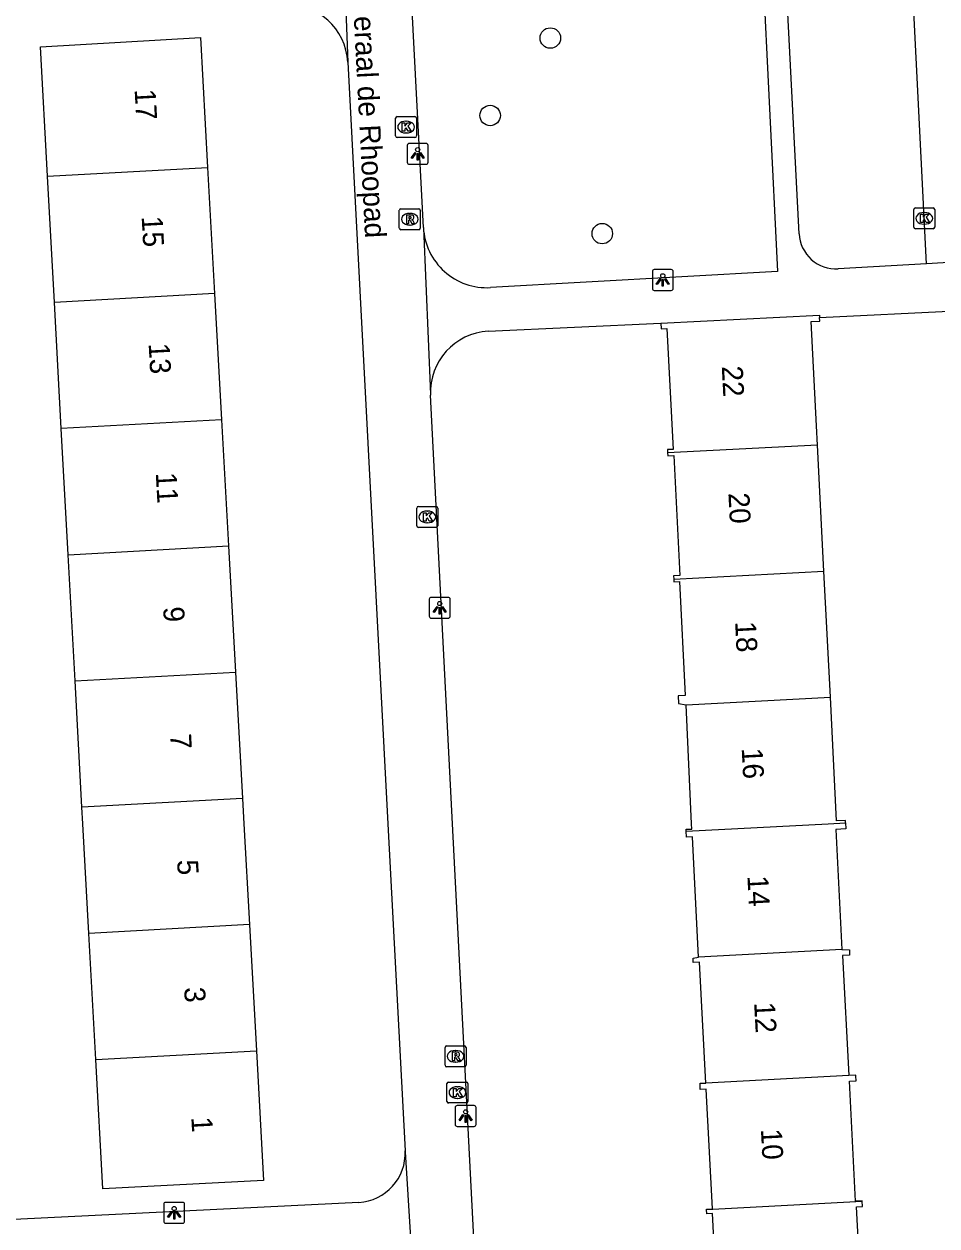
# Model space of a CAD drawing. Extents: x 161084 to 161928, y 385355 to 386522.
# Drawn here: x 161345.5 to 161389.2, y 385480.8 to 385538.2 of the extents above; entities that cross this region are included whole.
import ezdxf

# ---------------------------------------------------------------- set-up
doc = ezdxf.new("R2010")
doc.units = 0
for name, color, linetype in [('IMGEO_Boom', 7, 'Continuous'), ('IMGEO_Kolk', 7, 'Continuous'), ('IMGEO_Lichtpunt', 7, 'Continuous'), ('IMGEO_Muur', 7, 'Continuous'), ('IMGEO_Openbare_ruimte_label', 7, 'Continuous'), ('IMGEO_Pand', 7, 'Continuous'), ('IMGEO_Pand_nummerreeks', 7, 'Continuous'), ('IMGEO_Rijbaan_lokaal_open', 7, 'Continuous'), ('IMGEO_Rioolput', 7, 'Continuous'), ('IMGEO_Voetpad_open', 7, 'Continuous')]:
    doc.layers.add(name, color=color, linetype=linetype)

msp = doc.modelspace()

# ---------------------------------------------------------------- linework, layer by layer
at = {"layer": 'IMGEO_Boom'}
for centre in [(161370.683, 385537.575), (161367.806, 385533.87), (161373.165, 385528.221)]:
    msp.add_circle(centre, 0.489, dxfattribs=at)
at = {"layer": 'IMGEO_Kolk'}
for p, q in [((161363.289, 385532.891), (161363.289, 385533.743)), ((161363.364, 385533.817), (161364.216, 385533.817)), ((161363.777, 385533.597), (161363.802, 385533.597)), ((161364.29, 385533.743), (161364.29, 385532.891)), ((161363.8, 385533.037), (161363.775, 385533.037)), ((161364.216, 385532.817), (161363.364, 385532.817)), ((161388.056, 385528.527), (161388.056, 385529.379)), ((161388.131, 385529.453), (161388.983, 385529.453)), ((161388.544, 385529.233), (161388.569, 385529.233)), ((161389.057, 385529.379), (161389.057, 385528.527)), ((161388.983, 385528.453), (161388.131, 385528.453)), ((161388.567, 385528.673), (161388.542, 385528.673)), ((161364.303, 385514.248), (161364.303, 385515.1)), ((161364.378, 385515.174), (161365.23, 385515.174)), ((161364.791, 385514.954), (161364.816, 385514.954)), ((161365.304, 385515.1), (161365.304, 385514.248)), ((161365.23, 385514.174), (161364.378, 385514.174)), ((161364.814, 385514.394), (161364.789, 385514.394)), ((161365.818, 385487.651), (161366.67, 385487.651)), ((161365.743, 385486.725), (161365.743, 385487.577)), ((161366.231, 385487.431), (161366.256, 385487.431)), ((161366.744, 385487.577), (161366.744, 385486.725)), ((161366.67, 385486.651), (161365.818, 385486.651)), ((161366.254, 385486.871), (161366.229, 385486.871))]:
    msp.add_line(p, q, dxfattribs=at)
for points in [[(161363.289, 385532.891), (161363.289, 385533.743)], [(161363.364, 385533.817), (161364.216, 385533.817)], [(161364.29, 385533.743), (161364.29, 385532.891)], [(161363.61, 385533.517), (161363.733, 385533.517), (161363.733, 385533.366), (161363.863, 385533.517), (161364.027, 385533.517), (161363.881, 385533.366), (161364.034, 385533.117), (161363.882, 385533.117), (161363.797, 385533.281), (161363.733, 385533.214), (161363.733, 385533.117), (161363.61, 385533.117), (161363.61, 385533.517)], [(161364.216, 385532.817), (161363.364, 385532.817)], [(161388.056, 385528.527), (161388.056, 385529.379)], [(161388.131, 385529.453), (161388.983, 385529.453)], [(161388.377, 385529.153), (161388.5, 385529.153), (161388.5, 385529.002), (161388.63, 385529.153), (161388.794, 385529.153), (161388.648, 385529.002), (161388.801, 385528.753), (161388.649, 385528.753), (161388.564, 385528.917), (161388.5, 385528.85), (161388.5, 385528.753), (161388.377, 385528.753), (161388.377, 385529.153)], [(161389.057, 385529.379), (161389.057, 385528.527)], [(161388.983, 385528.453), (161388.131, 385528.453)], [(161364.303, 385514.248), (161364.303, 385515.1)], [(161364.378, 385515.174), (161365.23, 385515.174)], [(161364.624, 385514.874), (161364.747, 385514.874), (161364.747, 385514.723), (161364.877, 385514.874), (161365.041, 385514.874), (161364.895, 385514.723), (161365.048, 385514.474), (161364.896, 385514.474), (161364.811, 385514.638), (161364.747, 385514.571), (161364.747, 385514.474), (161364.624, 385514.474), (161364.624, 385514.874)], [(161365.304, 385515.1), (161365.304, 385514.248)], [(161365.23, 385514.174), (161364.378, 385514.174)], [(161365.818, 385487.651), (161366.67, 385487.651)], [(161365.743, 385486.725), (161365.743, 385487.577)], [(161366.064, 385487.351), (161366.187, 385487.351), (161366.187, 385487.2), (161366.317, 385487.351), (161366.481, 385487.351), (161366.335, 385487.2), (161366.488, 385486.951), (161366.336, 385486.951), (161366.251, 385487.115), (161366.187, 385487.048), (161366.187, 385486.951), (161366.064, 385486.951), (161366.064, 385487.351)], [(161366.744, 385487.577), (161366.744, 385486.725)], [(161366.67, 385486.651), (161365.818, 385486.651)]]:
    msp.add_lwpolyline(points, dxfattribs=at)
for centre, start, end in [((161363.366, 385533.741), 91.55205, 178.44795), ((161363.366, 385533.741), 91.55205, 178.44795), ((161364.214, 385533.741), 1.55205, 88.44795), ((161364.214, 385533.741), 1.55205, 88.44795), ((161363.366, 385532.893), 181.55205, 268.44795), ((161363.366, 385532.893), 181.55205, 268.44795), ((161364.214, 385532.893), 271.55205, 358.44795), ((161364.214, 385532.893), 271.55205, 358.44795), ((161388.133, 385529.377), 91.55205, 178.44795), ((161388.133, 385529.377), 91.55205, 178.44795), ((161388.981, 385529.377), 1.55205, 88.44795), ((161388.981, 385529.377), 1.55205, 88.44795), ((161388.133, 385528.529), 181.55205, 268.44795), ((161388.133, 385528.529), 181.55205, 268.44795), ((161388.981, 385528.529), 271.55205, 358.44795), ((161388.981, 385528.529), 271.55205, 358.44795), ((161364.38, 385515.098), 91.55205, 178.44795), ((161364.38, 385515.098), 91.55205, 178.44795), ((161365.228, 385515.098), 1.55205, 88.44795), ((161365.228, 385515.098), 1.55205, 88.44795), ((161364.38, 385514.25), 181.55205, 268.44795), ((161364.38, 385514.25), 181.55205, 268.44795), ((161365.228, 385514.25), 271.55205, 358.44795), ((161365.228, 385514.25), 271.55205, 358.44795), ((161365.82, 385487.575), 91.55205, 178.44795), ((161365.82, 385487.575), 91.55205, 178.44795), ((161366.668, 385487.575), 1.55205, 88.44795), ((161366.668, 385487.575), 1.55205, 88.44795), ((161365.82, 385486.727), 181.55205, 268.44795), ((161365.82, 385486.727), 181.55205, 268.44795), ((161366.668, 385486.727), 271.55205, 358.44795), ((161366.668, 385486.727), 271.55205, 358.44795)]:
    msp.add_arc(centre, 0.0765, start, end, dxfattribs=at)
for centre, major_axis, ratio, start_param, end_param in [((161363.776, 385533.317), (-0.387, 0.002), 0.722429, 4.712389, 7.853982), ((161363.801, 385533.317), (-0.39, 0.002), 0.717154, 1.570796, 4.712389), ((161388.543, 385528.953), (-0.387, 0.002), 0.722429, 4.712389, 7.853982), ((161388.568, 385528.953), (-0.39, 0.002), 0.717154, 1.570796, 4.712389), ((161364.79, 385514.674), (-0.387, 0.002), 0.722429, 4.712389, 7.853982), ((161364.815, 385514.674), (-0.39, 0.002), 0.717154, 1.570796, 4.712389), ((161366.23, 385487.151), (-0.387, 0.002), 0.722429, 4.712389, 7.853982), ((161366.255, 385487.151), (-0.39, 0.002), 0.717154, 1.570796, 4.712389)]:
    msp.add_ellipse(centre, major_axis=major_axis, ratio=ratio, start_param=start_param, end_param=end_param, dxfattribs=at)
at = {"layer": 'IMGEO_Lichtpunt'}
for p, q in [((161363.848, 385532.439), (161363.848, 385531.632)), ((161363.848, 385532.439), (161363.848, 385531.632)), ((161364.75, 385532.534), (161363.942, 385532.534)), ((161364.75, 385532.534), (161363.942, 385532.534)), ((161364.844, 385531.632), (161364.844, 385532.439)), ((161364.844, 385531.632), (161364.844, 385532.439)), ((161363.942, 385531.538), (161364.75, 385531.538)), ((161363.942, 385531.538), (161364.75, 385531.538)), ((161375.56, 385526.409), (161375.56, 385525.602)), ((161375.56, 385526.409), (161375.56, 385525.602)), ((161376.462, 385526.504), (161375.654, 385526.504)), ((161376.462, 385526.504), (161375.654, 385526.504)), ((161376.556, 385525.602), (161376.556, 385526.409)), ((161376.556, 385525.602), (161376.556, 385526.409)), ((161375.654, 385525.508), (161376.462, 385525.508)), ((161375.654, 385525.508), (161376.462, 385525.508)), ((161364.9, 385510.735), (161364.9, 385509.928)), ((161364.9, 385510.735), (161364.9, 385509.928)), ((161365.802, 385510.83), (161364.994, 385510.83)), ((161365.802, 385510.83), (161364.994, 385510.83)), ((161365.896, 385509.928), (161365.896, 385510.735)), ((161365.896, 385509.928), (161365.896, 385510.735)), ((161364.994, 385509.834), (161365.802, 385509.834)), ((161364.994, 385509.834), (161365.802, 385509.834)), ((161367.038, 385486.526), (161366.23, 385486.526)), ((161367.038, 385486.526), (161366.23, 385486.526)), ((161366.136, 385486.431), (161366.136, 385485.624)), ((161366.136, 385486.431), (161366.136, 385485.624)), ((161367.132, 385485.624), (161367.132, 385486.431)), ((161367.132, 385485.624), (161367.132, 385486.431)), ((161366.23, 385485.53), (161367.038, 385485.53)), ((161366.23, 385485.53), (161367.038, 385485.53)), ((161353.11, 385481.9), (161352.302, 385481.9)), ((161353.11, 385481.9), (161352.302, 385481.9)), ((161352.208, 385481.805), (161352.208, 385480.998)), ((161352.208, 385481.805), (161352.208, 385480.998)), ((161353.204, 385480.998), (161353.204, 385481.805)), ((161353.204, 385480.998), (161353.204, 385481.805)), ((161352.302, 385480.904), (161353.11, 385480.904)), ((161352.302, 385480.904), (161353.11, 385480.904))]:
    msp.add_line(p, q, dxfattribs=at)
for points in [[(161364.222, 385532.103), (161364.261, 385532.075), (161364.073, 385531.813), (161364.035, 385531.84), (161364.222, 385532.103)], [(161364.324, 385532.055), (161364.371, 385532.055), (161364.371, 385531.733), (161364.324, 385531.733), (161364.324, 385532.055)], [(161364.434, 385532.075), (161364.472, 385532.102), (161364.659, 385531.84), (161364.62, 385531.812), (161364.434, 385532.075)], [(161375.934, 385526.073), (161375.973, 385526.045), (161375.785, 385525.783), (161375.747, 385525.81), (161375.934, 385526.073)], [(161376.036, 385526.025), (161376.083, 385526.025), (161376.083, 385525.703), (161376.036, 385525.703), (161376.036, 385526.025)], [(161376.146, 385526.045), (161376.184, 385526.072), (161376.371, 385525.81), (161376.332, 385525.782), (161376.146, 385526.045)], [(161365.274, 385510.399), (161365.313, 385510.371), (161365.125, 385510.109), (161365.087, 385510.136), (161365.274, 385510.399)], [(161365.376, 385510.351), (161365.423, 385510.351), (161365.423, 385510.029), (161365.376, 385510.029), (161365.376, 385510.351)], [(161365.486, 385510.371), (161365.524, 385510.398), (161365.711, 385510.136), (161365.672, 385510.108), (161365.486, 385510.371)], [(161366.51, 385486.095), (161366.549, 385486.067), (161366.361, 385485.805), (161366.323, 385485.832), (161366.51, 385486.095)], [(161366.612, 385486.047), (161366.659, 385486.047), (161366.659, 385485.725), (161366.612, 385485.725), (161366.612, 385486.047)], [(161366.722, 385486.067), (161366.76, 385486.094), (161366.947, 385485.832), (161366.908, 385485.804), (161366.722, 385486.067)], [(161352.582, 385481.469), (161352.621, 385481.441), (161352.433, 385481.179), (161352.395, 385481.206), (161352.582, 385481.469)], [(161352.684, 385481.421), (161352.731, 385481.421), (161352.731, 385481.099), (161352.684, 385481.099), (161352.684, 385481.421)], [(161352.794, 385481.441), (161352.832, 385481.468), (161353.019, 385481.206), (161352.98, 385481.178), (161352.794, 385481.441)]]:
    msp.add_lwpolyline(points, dxfattribs=at)
for centre in [(161364.347, 385532.237), (161376.059, 385526.207), (161365.399, 385510.533), (161366.635, 385486.229), (161352.707, 385481.603)]:
    msp.add_circle(centre, 0.0994, dxfattribs=at)
for centre, start, end in [((161363.942, 385532.439), 90, 180), ((161363.942, 385532.439), 90, 180), ((161364.75, 385532.439), 0, 90), ((161364.75, 385532.439), 0, 90), ((161363.942, 385531.632), 180, 270), ((161363.942, 385531.632), 180, 270), ((161364.75, 385531.632), 270, 0), ((161364.75, 385531.632), 270, 360), ((161375.654, 385526.409), 90, 180), ((161375.654, 385526.409), 90, 180), ((161376.462, 385526.409), 0, 90), ((161376.462, 385526.409), 0, 90), ((161375.654, 385525.602), 180, 270), ((161375.654, 385525.602), 180, 270), ((161376.462, 385525.602), 270, 0), ((161376.462, 385525.602), 270, 360), ((161364.994, 385510.735), 90, 180), ((161364.994, 385510.735), 90, 180), ((161365.802, 385510.735), 0, 90), ((161365.802, 385510.735), 0, 90), ((161364.994, 385509.928), 180, 270), ((161364.994, 385509.928), 180, 270), ((161365.802, 385509.928), 270, 0), ((161365.802, 385509.928), 270, 360), ((161366.23, 385486.431), 90, 180), ((161366.23, 385486.431), 90, 180), ((161367.038, 385486.431), 0, 90), ((161367.038, 385486.431), 0, 90), ((161366.23, 385485.624), 180, 270), ((161366.23, 385485.624), 180, 270), ((161367.038, 385485.624), 270, 0), ((161367.038, 385485.624), 270, 360), ((161352.302, 385481.805), 90, 180), ((161352.302, 385481.805), 90, 180), ((161353.11, 385481.805), 0, 90), ((161353.11, 385481.805), 0, 90), ((161352.302, 385480.998), 180, 270), ((161352.302, 385480.998), 180, 270), ((161353.11, 385480.998), 270, 0), ((161353.11, 385480.998), 270, 360)]:
    msp.add_arc(centre, 0.0946, start, end, dxfattribs=at)
at = {"layer": 'IMGEO_Muur'}
msp.add_lwpolyline([(161383.553, 385524.217), (161390.069, 385524.53)], dxfattribs=at)
at = {"layer": 'IMGEO_Pand'}
for points in [[(161346.652, 385530.97), (161346.314, 385537.16), (161353.963, 385537.598), (161354.305, 385531.391)], [(161346.652, 385530.97), (161354.305, 385531.391)], [(161354.305, 385531.391), (161354.638, 385525.356)], [(161346.982, 385524.935), (161346.652, 385530.97)], [(161354.638, 385525.356), (161346.982, 385524.935)], [(161354.638, 385525.356), (161354.97, 385519.321)], [(161347.311, 385518.9), (161346.982, 385524.935)], [(161375.962, 385523.935), (161381.651, 385524.226), (161383.548, 385524.323), (161383.553, 385524.217)], [(161375.962, 385523.935), (161375.976, 385523.669), (161376.257, 385523.684), (161376.553, 385517.905), (161376.283, 385517.892), (161376.291, 385517.732)], [(161383.458, 385518.106), (161383.411, 385519.029), (161383.155, 385524.022), (161383.562, 385524.043), (161383.553, 385524.217)], [(161354.97, 385519.321), (161347.311, 385518.9)], [(161354.97, 385519.321), (161355.303, 385513.286)], [(161347.641, 385512.864), (161347.311, 385518.9)], [(161383.458, 385518.106), (161376.291, 385517.732)], [(161383.762, 385512.078), (161383.458, 385518.106)], [(161376.291, 385517.732), (161376.298, 385517.596), (161376.579, 385517.61), (161376.873, 385511.88), (161376.571, 385511.865), (161376.579, 385511.703)], [(161347.641, 385512.864), (161355.303, 385513.286)], [(161355.303, 385513.286), (161355.635, 385507.252)], [(161347.97, 385506.83), (161347.641, 385512.864)], [(161376.579, 385511.703), (161383.762, 385512.078)], [(161384.066, 385506.05), (161383.762, 385512.078)], [(161376.579, 385511.703), (161376.585, 385511.576), (161376.853, 385511.589), (161377.132, 385506.144), (161376.789, 385506.127), (161376.809, 385505.747), (161377.176, 385505.69)], [(161347.97, 385506.83), (161355.635, 385507.252)], [(161355.635, 385507.252), (161355.968, 385501.217)], [(161348.3, 385500.795), (161347.97, 385506.83)], [(161377.176, 385505.69), (161384.066, 385506.05)], [(161384.79, 385500.043), (161384.783, 385500.162), (161384.364, 385500.14), (161384.066, 385506.05)], [(161377.181, 385499.646), (161377.176, 385499.739), (161377.449, 385499.752), (161377.438, 385500), (161377.176, 385505.69)], [(161355.968, 385501.217), (161348.3, 385500.795)], [(161355.968, 385501.217), (161356.035, 385500), (161356.301, 385495.182)], [(161348.628, 385494.76), (161348.343, 385500), (161348.3, 385500.795)], [(161377.181, 385499.646), (161383.961, 385500), (161384.79, 385500.043)], [(161384.79, 385500.043), (161384.808, 385499.756), (161384.323, 385499.727), (161384.62, 385493.99)], [(161377.773, 385493.632), (161377.476, 385499.373), (161377.195, 385499.359), (161377.181, 385499.646)], [(161356.301, 385495.182), (161348.628, 385494.76)], [(161356.301, 385495.182), (161356.634, 385489.147)], [(161348.956, 385488.725), (161348.628, 385494.76)], [(161384.62, 385493.99), (161377.773, 385493.632)], [(161384.62, 385493.99), (161384.975, 385493.97), (161384.986, 385493.721), (161384.652, 385493.703), (161384.949, 385487.964)], [(161378.115, 385487.607), (161377.817, 385493.388), (161377.514, 385493.372), (161377.505, 385493.583), (161377.773, 385493.632)], [(161356.634, 385489.147), (161356.976, 385482.938), (161349.291, 385482.551), (161348.956, 385488.725)], [(161348.956, 385488.725), (161356.634, 385489.147)], [(161378.149, 385481.564), (161378.148, 385481.581), (161378.434, 385481.593), (161378.139, 385487.307), (161377.852, 385487.292), (161377.84, 385487.563), (161377.839, 385487.595), (161378.115, 385487.607)], [(161384.949, 385487.964), (161378.115, 385487.607)], [(161385.591, 385481.953), (161385.59, 385481.972), (161385.276, 385481.958), (161384.979, 385487.7), (161385.299, 385487.717), (161385.288, 385487.936), (161385.286, 385487.981), (161384.949, 385487.964)], [(161378.149, 385481.564), (161385.591, 385481.953)], [(161385.924, 385475.926), (161385.92, 385476.002), (161385.615, 385475.985), (161385.32, 385481.688), (161385.602, 385481.703), (161385.591, 385481.953)], [(161378.493, 385475.538), (161378.493, 385475.543), (161378.731, 385475.557), (161378.431, 385481.367), (161378.158, 385481.352), (161378.149, 385481.564)]]:
    msp.add_lwpolyline(points, dxfattribs=at)
at = {"layer": 'IMGEO_Rijbaan_lokaal_open'}
for points in [[(161388.666, 385526.781), (161387.919, 385541.732)], [(161392.115, 385526.978), (161388.666, 385526.781)]]:
    msp.add_lwpolyline(points, dxfattribs=at)
at = {"layer": 'IMGEO_Rioolput'}
for p, q in [((161363.467, 385528.485), (161363.467, 385529.337)), ((161363.542, 385529.411), (161364.394, 385529.411)), ((161363.955, 385529.191), (161363.98, 385529.191)), ((161364.468, 385529.337), (161364.468, 385528.485)), ((161364.394, 385528.411), (161363.542, 385528.411)), ((161363.978, 385528.631), (161363.953, 385528.631)), ((161365.728, 385489.382), (161366.58, 385489.382)), ((161365.653, 385488.456), (161365.653, 385489.308)), ((161366.141, 385489.162), (161366.166, 385489.162)), ((161366.654, 385489.308), (161366.654, 385488.456)), ((161366.58, 385488.382), (161365.728, 385488.382)), ((161366.164, 385488.602), (161366.139, 385488.602))]:
    msp.add_line(p, q, dxfattribs=at)
for points in [[(161363.467, 385528.485), (161363.467, 385529.337)], [(161363.542, 385529.411), (161364.394, 385529.411)], [(161364.056, 385529.109), (161363.804, 385529.111), (161363.804, 385528.711)], [(161363.982, 385529.03), (161363.928, 385529.03), (161363.928, 385528.949)], [(161364.468, 385529.337), (161364.468, 385528.485)], [(161364.394, 385528.411), (161363.542, 385528.411)], [(161363.804, 385528.711), (161363.928, 385528.711), (161363.928, 385528.873), (161363.939, 385528.873)], [(161363.928, 385528.949), (161363.98, 385528.949)], [(161363.986, 385528.844), (161364.057, 385528.711), (161364.197, 385528.711), (161364.132, 385528.837)], [(161365.728, 385489.382), (161366.58, 385489.382)], [(161365.653, 385488.456), (161365.653, 385489.308)], [(161366.242, 385489.08), (161365.99, 385489.082), (161365.99, 385488.682)], [(161365.99, 385488.682), (161366.114, 385488.682), (161366.114, 385488.844), (161366.125, 385488.844)], [(161366.168, 385489.001), (161366.114, 385489.001), (161366.114, 385488.92)], [(161366.114, 385488.92), (161366.166, 385488.92)], [(161366.172, 385488.815), (161366.243, 385488.682), (161366.383, 385488.682), (161366.318, 385488.808)], [(161366.654, 385489.308), (161366.654, 385488.456)], [(161366.58, 385488.382), (161365.728, 385488.382)]]:
    msp.add_lwpolyline(points, dxfattribs=at)
for centre, radius, start, end in [((161363.544, 385529.335), 0.0765, 91.55205, 178.44795), ((161363.544, 385529.335), 0.0765, 91.55205, 178.44795), ((161363.988, 385528.934), 0.0964, 77.00612, 93.18647), ((161364.002, 385528.991), 0.0378, 276.66336, 79.67722), ((161364.055, 385528.999), 0.109, 350.36119, 89.41601), ((161364.053, 385528.999), 0.112, 277.58423, 350.98172), ((161364.392, 385529.335), 0.0765, 1.55205, 88.44795), ((161364.392, 385529.335), 0.0765, 1.55205, 88.44795), ((161363.544, 385528.487), 0.0765, 181.55205, 268.44795), ((161363.544, 385528.487), 0.0765, 181.55205, 268.44795), ((161363.938, 385528.82), 0.0533, 26.02933, 88.69889), ((161363.964, 385529.138), 0.19, 274.7715, 282.96867), ((161364.037, 385528.784), 0.108, 29.51342, 73.79051), ((161364.392, 385528.487), 0.0765, 271.55205, 358.44795), ((161364.392, 385528.487), 0.0765, 271.55205, 358.44795), ((161365.73, 385489.306), 0.0765, 91.55205, 178.44795), ((161365.73, 385489.306), 0.0765, 91.55205, 178.44795), ((161366.578, 385489.306), 0.0765, 1.55205, 88.44795), ((161366.578, 385489.306), 0.0765, 1.55205, 88.44795), ((161366.124, 385488.791), 0.0533, 26.02933, 88.69889), ((161366.15, 385489.109), 0.19, 274.7715, 282.96867), ((161366.174, 385488.905), 0.0964, 77.00612, 93.18647), ((161366.188, 385488.962), 0.0378, 276.66336, 79.67722), ((161366.241, 385488.97), 0.109, 350.36119, 89.41601), ((161366.239, 385488.97), 0.112, 277.58423, 350.98172), ((161366.223, 385488.755), 0.108, 29.51342, 73.79051), ((161365.73, 385488.458), 0.0765, 181.55205, 268.44795), ((161365.73, 385488.458), 0.0765, 181.55205, 268.44795), ((161366.578, 385488.458), 0.0765, 271.55205, 358.44795), ((161366.578, 385488.458), 0.0765, 271.55205, 358.44795)]:
    msp.add_arc(centre, radius, start, end, dxfattribs=at)
for centre, major_axis, ratio, start_param, end_param in [((161363.954, 385528.911), (-0.387, 0.002), 0.722429, 4.712389, 7.853982), ((161363.979, 385528.911), (-0.39, 0.002), 0.717154, 1.570796, 4.712389), ((161366.14, 385488.882), (-0.387, 0.002), 0.722429, 4.712389, 7.853982), ((161366.165, 385488.882), (-0.39, 0.002), 0.717154, 1.570796, 4.712389)]:
    msp.add_ellipse(centre, major_axis=major_axis, ratio=ratio, start_param=start_param, end_param=end_param, dxfattribs=at)
at = {"layer": 'IMGEO_Voetpad_open'}
for points in [[(161364.617, 385528.51), (161362.888, 385561.798)], [(161360.681, 385544.392), (161360.7, 385544.287), (161361.004, 385536.419)], [(161380.802, 385541.342), (161381.537, 385526.414), (161367.825, 385525.64)], [(161382.572, 385528.215), (161382.007, 385539.366)], [(161361.004, 385536.419), (161362.922, 385500), (161363.746, 385484.359)], [(161364.617, 385528.51), (161364.615, 385528.479), (161364.955, 385520.547), (161364.961, 385520.497)], [(161388.666, 385526.781), (161384.439, 385526.54)], [(161383.553, 385524.217), (161390.069, 385524.53)], [(161367.718, 385523.553), (161375.962, 385523.935)], [(161368.313, 385455.102), (161366.012, 385500), (161364.961, 385520.497)], [(161363.746, 385484.359), (161363.753, 385484.323), (161364.139, 385477.899), (161364.135, 385477.846)], [(161361.528, 385481.899), (161341.805, 385480.919)]]:
    msp.add_lwpolyline(points, dxfattribs=at)
for centre, radius, start, end in [((161358.1, 385536.27), 2.908, 2.93456, 92.90247), ((161367.654, 385528.677), 3.042, 183.14431, 273.22162), ((161384.337, 385528.305), 1.768, 182.91345, 273.29211), ((161367.877, 385520.638), 2.92, 93.12525, 182.76374), ((161361.402, 385484.243), 2.347, 273.08034, 2.84237)]:
    msp.add_arc(centre, radius, start, end, dxfattribs=at)

# ---------------------------------------------------------------- texts
at = {"layer": 'IMGEO_Openbare_ruimte_label'}
msp.add_text('Generaal de Rhoopad', height=1, rotation=272.92247, dxfattribs=at).set_placement((161361.163, 385541.131))
at = {"layer": 'IMGEO_Pand_nummerreeks'}
for s, rotation, p in [('17', 273.15509, (161350.815, 385535.115)), ('15', 273.15509, (161351.15, 385529.041)), ('13', 273.15509, (161351.484, 385522.968)), ('22', 272.98674, (161378.876, 385521.879)), ('11', 273.15509, (161351.826, 385516.782)), ('20', 272.98674, (161379.192, 385515.813)), ('9', 273.15509, (161352.179, 385510.362)), ('18', 272.98674, (161379.513, 385509.664)), ('7', 273.15509, (161352.514, 385504.289)), ('16', 272.9849, (161379.828, 385503.608)), ('5', 273.1566, (161352.845, 385498.265)), ('14', 273.05361, (161380.099, 385497.503)), ('3', 273.1566, (161353.181, 385492.172)), ('12', 273.05361, (161380.422, 385491.454)), ('1', 273.1566, (161353.524, 385485.965)), ('10', 273.05365, (161380.745, 385485.396))]:
    msp.add_text(s, height=1, rotation=rotation, dxfattribs=at).set_placement(p)

doc.saveas('drawing.dxf')
